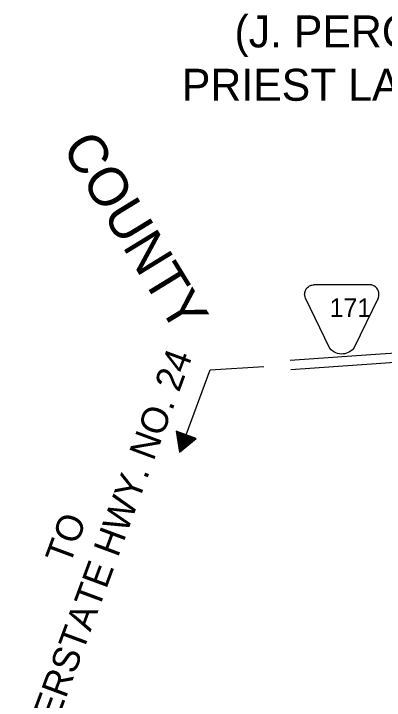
# Model space of a CAD drawing. Extents: x 1788175 to 1969470, y 584502 to 738744.
# Drawn here: x 1802187 to 1809536, y 640424 to 654036 of the extents above; entities that cross this region are included whole.
import ezdxf

# ---------------------------------------------------------------- set-up
doc = ezdxf.new("R2010")
doc.units = 0
for name, color, linetype in [('DESIGN - DRAINAGE - Bridges', 7, 'Continuous'), ('DESIGN - ROW - Easement Linework and Patterning', 7, 'Continuous'), ('DESIGN - TRAFFIC CONTROL PERMANENT - Signalization Text', 7, 'Continuous'), ('SURVEY - CONTROL with Text', 7, 'Continuous'), ('SURVEY - DRAINAGE - Natural Features', 7, 'Continuous')]:
    doc.layers.add(name, color=color, linetype=linetype)

msp = doc.modelspace()

# ---------------------------------------------------------------- linework, layer by layer
at = {"layer": 'DESIGN - ROW - Easement Linework and Patterning'}
for points in [[(1808450, 647415), (1807976, 648396), (1807965, 648423), (1807961, 648441), (1807958, 648459), (1807957, 648474), (1807958, 648492), (1807960, 648509), (1807966, 648532), (1807973, 648549), (1807980, 648565), (1807990, 648582), (1808001, 648595), (1808016, 648611), (1808030, 648623), (1808044, 648633), (1808056, 648640), (1808073, 648648), (1808088, 648653), (1808101, 648656), (1808123, 648660), (1808142, 648661)], [(1809413, 648396), (1809419, 648413), (1809427, 648437), (1809430, 648453), (1809431, 648474), (1809431, 648489), (1809429, 648507), (1809424, 648529), (1809417, 648548), (1809410, 648562), (1809402, 648577), (1809390, 648593), (1809377, 648607), (1809359, 648623), (1809344, 648633), (1809330, 648641), (1809316, 648648), (1809299, 648653), (1809280, 648658), (1809266, 648660), (1809247, 648661), (1808142, 648661)], [(1809413, 648396), (1808940, 647418), (1808925, 647398), (1808910, 647382), (1808897, 647368), (1808869, 647345), (1808847, 647331), (1808823, 647318), (1808790, 647305), (1808752, 647295), (1808721, 647290), (1808686, 647289), (1808648, 647292), (1808608, 647302), (1808572, 647315), (1808536, 647334), (1808514, 647349), (1808485, 647374), (1808450, 647415)]]:
    msp.add_lwpolyline(points, dxfattribs=at)
at = {"layer": 'DESIGN - TRAFFIC CONTROL PERMANENT - Signalization Text'}
for p, q in [((1805605, 645686), (1806081, 646973)), ((1805803, 645612), (1805407, 645759)), ((1805407, 645759), (1805478, 645342)), ((1805780, 645611), (1805421, 645742)), ((1805421, 645742), (1805485, 645362)), ((1805749, 645608), (1805439, 645723)), ((1805439, 645723), (1805489, 645372)), ((1805723, 645605), (1805462, 645702)), ((1805462, 645702), (1805496, 645391)), ((1805704, 645602), (1805477, 645687)), ((1805477, 645687), (1805502, 645408)), ((1805677, 645597), (1805497, 645668)), ((1805497, 645668), (1805511, 645436)), ((1805478, 645342), (1805803, 645612)), ((1805485, 645361), (1805780, 645611)), ((1805485, 645362), (1805749, 645608)), ((1805489, 645372), (1805723, 645605)), ((1805496, 645391), (1805704, 645602)), ((1805502, 645408), (1805677, 645597)), ((1805511, 645436), (1805648, 645593)), ((1805648, 645593), (1805517, 645642)), ((1805517, 645642), (1805522, 645468)), ((1805522, 645468), (1805624, 645587)), ((1805534, 645623), (1805531, 645496)), ((1805531, 645496), (1805606, 645583)), ((1805624, 645587), (1805534, 645623)), ((1805549, 645604), (1805545, 645530)), ((1805545, 645530), (1805585, 645575)), ((1805606, 645583), (1805549, 645604)), ((1805560, 645586), (1805558, 645559)), ((1805558, 645559), (1805571, 645573)), ((1805585, 645575), (1805560, 645586))]:
    msp.add_line(p, q, dxfattribs=at)
msp.add_lwpolyline([(1806081, 646973), (1807150, 647042)], dxfattribs=at)
at = {"layer": 'SURVEY - CONTROL with Text'}
for points in [[(1810369, 647349), (1809364, 647278)], [(1809365, 647278), (1807669, 647158)], [(1810382, 647165), (1809378, 647093)], [(1809377, 647093), (1807682, 646974)]]:
    msp.add_lwpolyline(points, dxfattribs=at)

# ---------------------------------------------------------------- texts
at = {"layer": 'DESIGN - DRAINAGE - Bridges'}
for s, p in [('(J. PERCY', (1806566, 653369)), ('PRIEST LAKE)', (1805523, 652311))]:
    msp.add_text(s, height=634, dxfattribs=at).set_placement(p)
at = {"layer": 'DESIGN - ROW - Easement Linework and Patterning'}
msp.add_text('171', height=369.6, dxfattribs=at).set_placement((1808452, 648023))
at = {"layer": 'DESIGN - TRAFFIC CONTROL PERMANENT - Signalization Text'}
for s, p in [('INTERSTATE HWY. NO. 24', (1802660, 638936)), ('TO', (1803297, 643086))]:
    msp.add_text(s, height=528, rotation=69.6951, dxfattribs=at).set_placement(p)
at = {"layer": 'SURVEY - DRAINAGE - Natural Features'}
msp.add_text('COUNTY', height=775, rotation=301.4768, dxfattribs=at).set_placement((1803130, 651387))

doc.saveas('drawing.dxf')
